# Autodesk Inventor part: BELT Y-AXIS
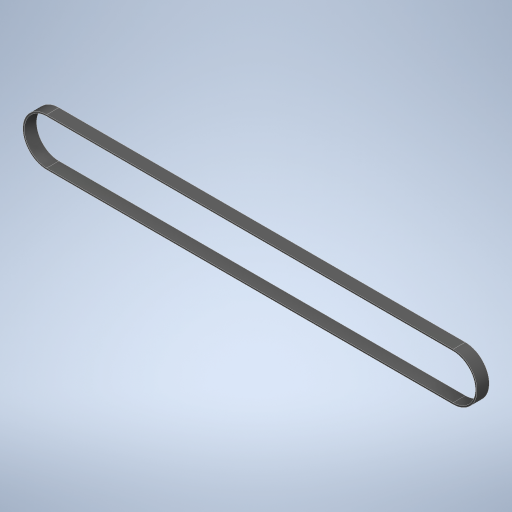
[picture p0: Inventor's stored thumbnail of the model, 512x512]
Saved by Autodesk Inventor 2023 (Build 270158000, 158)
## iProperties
Created: 2025-07
Part Number: BELT Y-AXIS
Material: Generic
Document SubType Name: Modeling
Designer: erjon
Density: 1 g/cm^3
Appearance: Default
Author: erjon
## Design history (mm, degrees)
feature "Base1"
body "Solid1"
